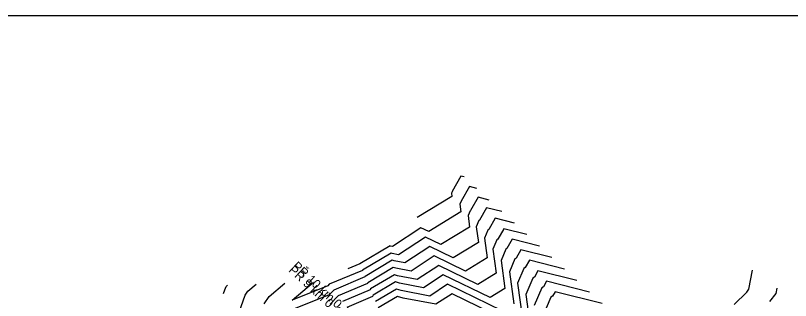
# Model space of a CAD drawing. Extents: x -549394 to -546608, y -1037055 to -1033629.
# Drawn here: x -548997 to -548203, y -1033921 to -1033629 of the extents above; entities that cross this region are included whole.
import ezdxf

# ---------------------------------------------------------------- set-up
doc = ezdxf.new("R2010")
doc.units = 0
for name, color, linetype in [('hlavni_vrst', 7, 'Continuous'), ('norm_vrst', 7, 'Continuous'), ('ram', 7, 'Continuous'), ('x_popis_pricne_rezy_C122', 7, 'Continuous')]:
    doc.layers.add(name, color=color, linetype=linetype)

msp = doc.modelspace()

# ---------------------------------------------------------------- linework, layer by layer
at = {"layer": 'hlavni_vrst'}
for p, q in [((-548522.91, -1033815.46), (-548530.68, -1033829.28)), ((-548511.36, -1033818.36), (-548522.91, -1033815.46)), ((-548531.13, -1033829.55), (-548533.17, -1033834.32)), ((-548533.17, -1033834.32), (-548531.54, -1033846.11)), ((-548530.68, -1033829.28), (-548531.13, -1033829.55)), ((-548531.54, -1033846.11), (-548560.91, -1033864.15)), ((-548576.79, -1033856.42), (-548604.23, -1033874.45)), ((-548560.91, -1033864.15), (-548576.79, -1033856.42)), ((-548611.94, -1033872.85), (-548641.22, -1033890.24)), ((-548610.83, -1033873.19), (-548611.94, -1033872.85)), ((-548604.23, -1033874.45), (-548610.83, -1033873.19)), ((-548479.08, -1033869.4), (-548483.92, -1033878.01)), ((-548447.2, -1033877.41), (-548479.08, -1033869.4)), ((-548485.18, -1033878.76), (-548490.83, -1033892.03)), ((-548483.92, -1033878.01), (-548485.18, -1033878.76)), ((-548641.34, -1033890.55), (-548675.25, -1033904.82)), ((-548641.22, -1033890.24), (-548641.34, -1033890.55)), ((-548245.4, -1033909.9), (-548241.65, -1033890.47)), ((-548490.83, -1033892.03), (-548486.31, -1033924.79)), ((-548713.35, -1033921.25), (-548691.5, -1033902.5)), ((-548676.8, -1033906.45), (-548713.35, -1033921.25)), ((-548675.25, -1033904.82), (-548676.8, -1033906.45)), ((-548554.07, -1033904.76), (-548572.44, -1033916.84)), ((-548498.07, -1033932.01), (-548554.07, -1033904.76)), ((-548606.36, -1033909.81), (-548627.8, -1033922.53)), ((-548601.49, -1033911.27), (-548606.36, -1033909.81)), ((-548572.44, -1033916.84), (-548601.49, -1033911.27)), ((-548260.39, -1033925.45), (-548247.65, -1033912.86)), ((-548247.65, -1033912.86), (-548245.4, -1033909.9))]:
    msp.add_line(p, q, dxfattribs=at)
at = {"layer": 'norm_vrst'}
for p, q in [((-548540.44, -1033793.88), (-548549.39, -1033809.78)), ((-548537.02, -1033794.74), (-548540.44, -1033793.88)), ((-548549.52, -1033809.86), (-548550.1, -1033811.24)), ((-548550.1, -1033811.24), (-548549.63, -1033814.64)), ((-548549.39, -1033809.78), (-548549.52, -1033809.86)), ((-548531.67, -1033804.67), (-548540.03, -1033819.53)), ((-548524.19, -1033806.55), (-548531.67, -1033804.67)), ((-548549.63, -1033814.64), (-548585.1, -1033836.42)), ((-548540.32, -1033819.7), (-548541.64, -1033822.78)), ((-548541.64, -1033822.78), (-548540.59, -1033830.37)), ((-548540.03, -1033819.53), (-548540.32, -1033819.7)), ((-548514.14, -1033826.25), (-548521.33, -1033839.02)), ((-548498.53, -1033830.17), (-548514.14, -1033826.25)), ((-548540.59, -1033830.37), (-548573.47, -1033850.57)), ((-548521.94, -1033839.39), (-548524.7, -1033845.87)), ((-548521.33, -1033839.02), (-548521.94, -1033839.39)), ((-548505.38, -1033837.03), (-548511.98, -1033848.77)), ((-548485.69, -1033841.98), (-548505.38, -1033837.03)), ((-548581.34, -1033846.75), (-548610.59, -1033865.97)), ((-548573.47, -1033850.57), (-548581.34, -1033846.75)), ((-548524.7, -1033845.87), (-548522.5, -1033861.85)), ((-548512.75, -1033849.23), (-548516.23, -1033857.41)), ((-548511.98, -1033848.77), (-548512.75, -1033849.23)), ((-548496.61, -1033847.82), (-548502.63, -1033858.51)), ((-548472.86, -1033853.79), (-548496.61, -1033847.82)), ((-548516.23, -1033857.41), (-548513.45, -1033877.58)), ((-548503.56, -1033859.07), (-548507.77, -1033868.95)), ((-548502.63, -1033858.51), (-548503.56, -1033859.07)), ((-548487.85, -1033858.61), (-548493.28, -1033868.26)), ((-548460.03, -1033865.6), (-548487.85, -1033858.61)), ((-548613.06, -1033865.46), (-548643.91, -1033883.78)), ((-548612.7, -1033865.57), (-548613.06, -1033865.46)), ((-548610.59, -1033865.97), (-548612.7, -1033865.57)), ((-548572.25, -1033866.08), (-548597.88, -1033882.93)), ((-548548.34, -1033877.72), (-548572.25, -1033866.08)), ((-548522.5, -1033861.85), (-548548.34, -1033877.72)), ((-548507.77, -1033868.95), (-548504.4, -1033893.32)), ((-548494.37, -1033868.92), (-548499.3, -1033880.49)), ((-548493.28, -1033868.26), (-548494.37, -1033868.92)), ((-548610.82, -1033880.24), (-548638.54, -1033896.7)), ((-548608.96, -1033880.8), (-548610.82, -1033880.24)), ((-548597.88, -1033882.93), (-548608.96, -1033880.8)), ((-548567.7, -1033875.75), (-548591.52, -1033891.41)), ((-548535.77, -1033891.29), (-548567.7, -1033875.75)), ((-548513.45, -1033877.58), (-548535.77, -1033891.29)), ((-548499.3, -1033880.49), (-548495.36, -1033909.05)), ((-548470.32, -1033880.19), (-548474.57, -1033887.75)), ((-548434.37, -1033889.22), (-548470.32, -1033880.19)), ((-548643.93, -1033883.85), (-548656.12, -1033888.97)), ((-548643.91, -1033883.78), (-548643.93, -1033883.85)), ((-548609.71, -1033887.63), (-548635.86, -1033903.16)), ((-548607.1, -1033888.42), (-548609.71, -1033887.63)), ((-548591.52, -1033891.41), (-548607.1, -1033888.42)), ((-548563.16, -1033885.42), (-548585.16, -1033899.88)), ((-548523.21, -1033904.87), (-548563.16, -1033885.42)), ((-548475.99, -1033888.6), (-548482.37, -1033903.58)), ((-548474.57, -1033887.75), (-548475.99, -1033888.6)), ((-548638.75, -1033897.25), (-548670.77, -1033910.73)), ((-548638.54, -1033896.7), (-548638.75, -1033897.25)), ((-548608.59, -1033895.02), (-548633.17, -1033909.62)), ((-548605.23, -1033896.04), (-548608.59, -1033895.02)), ((-548585.16, -1033899.88), (-548605.23, -1033896.04)), ((-548558.62, -1033895.09), (-548578.8, -1033908.36)), ((-548510.64, -1033918.44), (-548558.62, -1033895.09)), ((-548504.4, -1033893.32), (-548523.21, -1033904.87)), ((-548466.8, -1033898.44), (-548473.9, -1033915.12)), ((-548465.22, -1033897.5), (-548466.8, -1033898.44)), ((-548461.55, -1033890.98), (-548465.22, -1033897.5)), ((-548421.54, -1033901.03), (-548461.55, -1033890.98)), ((-548781.02, -1033907.17), (-548780.69, -1033906.66)), ((-548780.69, -1033906.66), (-548779.65, -1033905.77)), ((-548758.78, -1033911.98), (-548750.27, -1033904.68)), ((-548736.86, -1033917.29), (-548720.88, -1033903.59)), ((-548636.15, -1033903.96), (-548666.3, -1033916.64)), ((-548635.86, -1033903.16), (-548636.15, -1033903.96)), ((-548607.48, -1033902.41), (-548630.49, -1033916.07)), ((-548603.36, -1033903.65), (-548607.48, -1033902.41)), ((-548578.8, -1033908.36), (-548603.36, -1033903.65)), ((-548482.37, -1033903.58), (-548477.27, -1033940.53)), ((-548452.79, -1033901.76), (-548455.87, -1033907.25)), ((-548408.7, -1033912.83), (-548452.79, -1033901.76)), ((-548783.76, -1033914.17), (-548782.18, -1033910.38)), ((-548782.18, -1033910.38), (-548781.02, -1033907.17)), ((-548761.43, -1033916.07), (-548758.78, -1033911.98)), ((-548670.77, -1033910.73), (-548675.54, -1033915.76)), ((-548633.56, -1033910.66), (-548661.82, -1033922.55)), ((-548633.17, -1033909.62), (-548633.56, -1033910.66)), ((-548549.53, -1033914.43), (-548566.09, -1033925.31)), ((-548485.51, -1033945.59), (-548549.53, -1033914.43)), ((-548495.36, -1033909.05), (-548510.64, -1033918.44)), ((-548457.61, -1033908.29), (-548465.43, -1033926.66)), ((-548455.87, -1033907.25), (-548457.61, -1033908.29)), ((-548444.02, -1033912.55), (-548446.52, -1033916.99)), ((-548395.87, -1033924.64), (-548444.02, -1033912.55)), ((-548223.87, -1033922.62), (-548217.56, -1033914.31)), ((-548217.56, -1033914.31), (-548216.51, -1033908.86)), ((-548770.93, -1033942.25), (-548761.43, -1033916.07)), ((-548741.85, -1033924.97), (-548736.86, -1033917.29)), ((-548675.54, -1033915.76), (-548711.87, -1033930.47)), ((-548666.3, -1033916.64), (-548674.29, -1033925.07)), ((-548630.97, -1033917.36), (-548657.34, -1033928.46)), ((-548630.49, -1033916.07), (-548630.97, -1033917.36)), ((-548605.25, -1033917.2), (-548625.12, -1033928.99)), ((-548599.62, -1033918.89), (-548605.25, -1033917.2)), ((-548566.09, -1033925.31), (-548599.62, -1033918.89)), ((-548473.9, -1033915.12), (-548468.22, -1033956.26)), ((-548448.42, -1033918.13), (-548456.97, -1033938.2)), ((-548446.52, -1033916.99), (-548448.42, -1033918.13))]:
    msp.add_line(p, q, dxfattribs=at)
at = {"layer": 'ram'}
msp.add_lwpolyline([(-549394.28, -1037054.81), (-549394.28, -1033629.11), (-546608.04, -1033629.11), (-546608.04, -1037054.81), (-549394.28, -1037054.81)], dxfattribs=at)

# ---------------------------------------------------------------- texts
at = {"layer": 'x_popis_pricne_rezy_C122'}
for s, p in [('PŘ 10 km 0.4056', (-548713.82, -1033887.18)), ('PŘ 9 km 0.4000', (-548717.59, -1033891.25))]:
    msp.add_text(s, height=9.0627, rotation=317.20498, dxfattribs=at).set_placement(p)

doc.saveas('drawing.dxf')
